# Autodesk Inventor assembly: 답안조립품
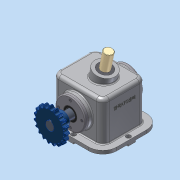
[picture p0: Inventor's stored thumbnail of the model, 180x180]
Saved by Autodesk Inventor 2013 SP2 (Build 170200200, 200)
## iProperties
Created: 2014-11
Part Number: 답안조립품
Document SubType Name: Assembly
Designer: dgall
Author: dgall
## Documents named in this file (13)
- C:\Documents and Settings\dgall\바탕 화면\441122V1009\답안조립품.iam
- C:\Documents and Settings\dgall\바탕 화면\441122V1009\1본체.ipt
- C:\Documents and Settings\dgall\바탕 화면\441122V1009\슬라이드.ipt
- C:\Documents and Settings\dgall\바탕 화면\441122V1009\앞커버.ipt
- C:\Documents and Settings\dgall\바탕 화면\441122V1009\오일실.ipt
- C:\Documents and Settings\dgall\바탕 화면\441122V1009\키 8x8.ipt
- C:\Documents and Settings\dgall\바탕 화면\441122V1009\편심축.ipt
- C:\Documents and Settings\dgall\바탕 화면\441122V1009\M4x0.5.ipt
- C:\Documents and Settings\dgall\바탕 화면\441122V1009\5-체인 스프로킷.ipt
- C:\Documents and Settings\dgall\바탕 화면\441122V1009\뒤커버.ipt
- C:\Documents and Settings\dgall\바탕 화면\441122V1009\멈춤나사 M5x0.5.ipt
- C:\Documents and Settings\dgall\바탕 화면\441122V1009\베어링 6205.ipt
- C:\Documents and Settings\dgall\바탕 화면\441122V1009\부시.ipt
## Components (10 placed, 3 different names)
1. 1본체:1
2. 5-체인 스프로킷:1
3. M4x0.5:1
4. M4x0.5:3
5. M4x0.5:4
6. M4x0.5:5
7. M4x0.5:2
8. M4x0.5:6
9. M4x0.5:7
10. M4x0.5:8
